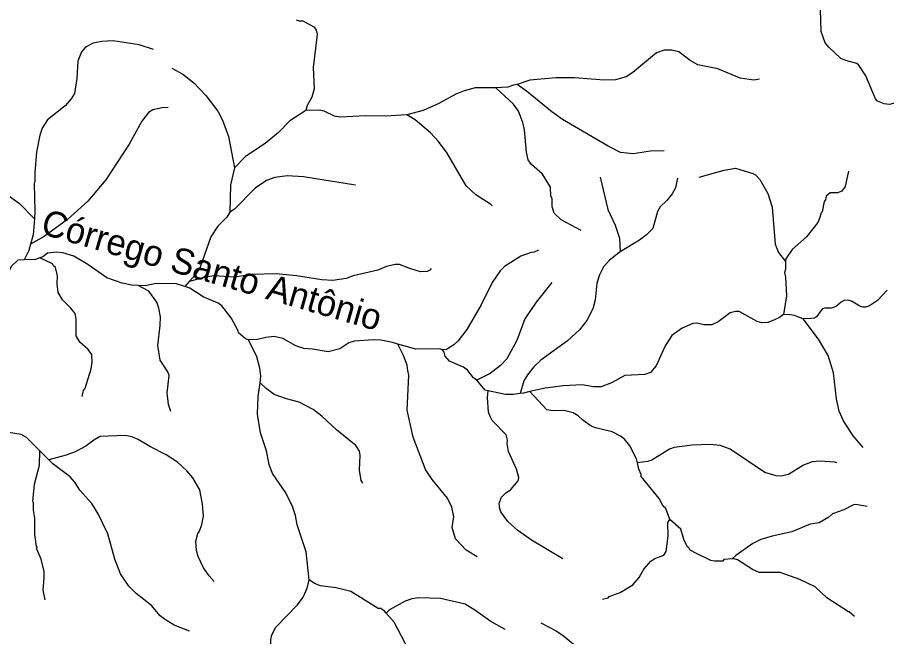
# Model space of a CAD drawing. Extents: x 280.4 to 335.6, y 8893.9 to 8949.5.
# Drawn here: x 307.39 to 314.12, y 8941.25 to 8946.04 of the extents above; entities that cross this region are included whole.
import ezdxf
from ezdxf.enums import TextEntityAlignment as Align

# ---------------------------------------------------------------- set-up
doc = ezdxf.new("R2010")
doc.units = 0
doc.header["$LTSCALE"] = 0.064
doc.layers.add('61', color=7, linetype='Continuous')
doc.layers.add('7', color=7, linetype='Continuous', lineweight=25)

msp = doc.modelspace()

# ---------------------------------------------------------------- linework, layer by layer
at = {"layer": '7'}
for p, q in [((308.7204, 8943.9928), (308.687, 8943.9546)), ((307.6334, 8942.6142), (307.5641, 8942.683))]:
    msp.add_line(p, q, dxfattribs=at)
for points in [[(314.448, 8945.3983), (314.3467, 8945.4085), (314.2833, 8945.4022), (314.1401, 8945.364), (314.0998, 8945.3684), (314.0476, 8945.3888), (314.0315, 8945.4072), (313.958, 8945.5861), (313.903, 8945.6679), (313.8884, 8945.6805), (313.803, 8945.7029), (313.7647, 8945.7193), (313.6718, 8945.8069), (313.6441, 8945.8408), (313.6111, 8945.9293), (313.6077, 8946.0979), (313.6025, 8946.141)], [(309.548, 8946.0198), (309.571, 8946.0106), (309.6004, 8946.0101), (309.6858, 8945.9654), (309.7023, 8945.938), (309.7103, 8945.9059), (309.6803, 8945.6503), (309.6861, 8945.4853), (309.6704, 8945.419), (309.6341, 8945.3565), (309.6217, 8945.3181)], [(308.4439, 8945.7878), (308.3334, 8945.826), (308.1312, 8945.8548), (308.0423, 8945.85), (307.9774, 8945.8374), (307.9177, 8945.8068), (307.8853, 8945.7716), (307.8572, 8945.6994), (307.8504, 8945.5644), (307.8314, 8945.4491), (307.8063, 8945.4074), (307.7587, 8945.3521), (307.6228, 8945.246), (307.5824, 8945.1796), (307.5635, 8945.1264), (307.537, 8944.9937), (307.5243, 8944.8344), (307.5258, 8944.773), (307.5198, 8944.7505), (307.5258, 8944.537), (307.5217, 8944.4792)], [(313.1337, 8945.5583), (313.0897, 8945.5528), (312.985, 8945.5672), (312.8111, 8945.6395), (312.6579, 8945.6709), (312.5981, 8945.7033), (312.5107, 8945.7699), (312.4524, 8945.7844), (312.3971, 8945.7845), (312.3366, 8945.7643), (312.1549, 8945.6103), (312.1018, 8945.5787), (312.0188, 8945.5543), (311.931, 8945.551), (311.7014, 8945.5701), (311.5576, 8945.5701), (311.3568, 8945.5526), (311.2599, 8945.5173), (311.2588, 8945.5172)], [(308.5856, 8945.6448), (308.6701, 8945.5975), (308.7545, 8945.5312), (308.8493, 8945.4333), (308.9427, 8945.3126), (308.9782, 8945.2431), (309.024, 8945.1166), (309.0714, 8944.8728)], [(311.0925, 8945.4921), (311.0767, 8945.4911), (310.9347, 8945.4932), (310.8474, 8945.4693), (310.7841, 8945.444), (310.6528, 8945.372), (310.5322, 8945.3176), (310.4034, 8945.2835)], [(311.2588, 8945.5172), (311.2291, 8945.5137), (311.1865, 8945.4983), (311.0925, 8945.4921)], [(311.7552, 8944.3894), (311.5992, 8944.4715), (311.5455, 8944.5233), (311.529, 8944.5723), (311.5286, 8944.6353), (311.5194, 8944.6554), (311.5157, 8944.7239), (311.4551, 8944.8248), (311.3694, 8944.9002), (311.345, 8944.9361), (311.3321, 8944.9945), (311.3143, 8945.1678), (311.3013, 8945.2254), (311.268, 8945.311), (311.2295, 8945.367), (311.0925, 8945.4921)], [(312.3964, 8945.0052), (312.2901, 8945.0024), (312.1563, 8944.9818), (312.059, 8944.9918), (311.9638, 8945.0408), (311.61, 8945.2484), (311.5265, 8945.3073), (311.3321, 8945.4676), (311.2588, 8945.5172)], [(306.9119, 8945.3451), (306.985, 8945.155), (307.0241, 8945.013), (307.0618, 8944.9184), (307.102, 8944.8473), (307.2001, 8944.7447), (307.4053, 8944.5982), (307.5217, 8944.4792)], [(308.5582, 8945.3406), (308.5111, 8945.338), (308.4371, 8945.3226), (308.4048, 8945.3022), (308.3525, 8945.2336), (308.2541, 8945.0562), (308.0743, 8944.7802), (307.9339, 8944.6157), (307.7776, 8944.4732), (307.597, 8944.342), (307.4925, 8944.2825)], [(309.6217, 8945.3181), (309.4999, 8945.2379), (309.4115, 8945.1466), (309.3088, 8945.0611), (309.1569, 8944.962), (309.0714, 8944.8728)], [(310.4034, 8945.2835), (310.4029, 8945.2834), (310.2437, 8945.2727), (310.0814, 8945.2758), (309.8911, 8945.2663), (309.8438, 8945.2742), (309.7638, 8945.3107), (309.7272, 8945.3207), (309.6217, 8945.3181)], [(311.0653, 8944.5792), (311.0534, 8944.592), (310.9382, 8944.6641), (310.8634, 8944.7337), (310.7166, 8944.9873), (310.6489, 8945.0772), (310.5868, 8945.143), (310.47, 8945.2457), (310.4034, 8945.2835)], [(309.0714, 8944.8728), (309.0387, 8944.741), (309.0334, 8944.5305)], [(312.6678, 8944.8006), (312.8619, 8944.855), (312.9488, 8944.8696), (313.0826, 8944.8298), (313.1023, 8944.8188), (313.1381, 8944.784), (313.198, 8944.6752), (313.2319, 8944.569), (313.2558, 8944.2826), (313.2828, 8944.2178), (313.3355, 8944.1488)], [(310.0082, 8944.7405), (309.6057, 8944.804), (309.4785, 8944.812), (309.3833, 8944.7994), (309.3192, 8944.7757), (309.2304, 8944.7171), (309.0695, 8944.5536), (309.0334, 8944.5305)], [(311.9014, 8944.8023), (311.9605, 8944.5522), (312.0167, 8944.4291), (312.05, 8944.3291), (312.0566, 8944.2245)], [(313.824, 8944.8469), (313.7967, 8944.7285), (313.7716, 8944.6919), (313.738, 8944.6797), (313.6803, 8944.6789), (313.6503, 8944.6529), (313.6459, 8944.6267), (313.6353, 8944.6122), (313.6205, 8944.532), (313.6116, 8944.5255), (313.6027, 8944.4884), (313.5849, 8944.4516), (313.4992, 8944.339), (313.3882, 8944.2422), (313.3396, 8944.1696), (313.3355, 8944.1488)], [(312.4997, 8944.7943), (312.4832, 8944.7187), (312.4582, 8944.6719), (312.4205, 8944.6244), (312.3661, 8944.5716), (312.3441, 8944.5364), (312.3091, 8944.4049), (312.261, 8944.3546), (312.2054, 8944.3128), (312.0566, 8944.2245)], [(309.0334, 8944.5305), (309.0113, 8944.4907), (308.9423, 8944.4212), (308.8876, 8944.3396), (308.8048, 8944.1046), (308.7678, 8944.047), (308.7204, 8943.9928)], [(307.5217, 8944.4792), (307.513, 8944.3552), (307.4925, 8944.2825)], [(307.4925, 8944.2825), (307.4785, 8944.233), (307.4435, 8944.1612)], [(307.6919, 8944.2204), (307.6228, 8944.2136), (307.5861, 8944.1858), (307.5639, 8944.1774)], [(308.3245, 8943.9627), (308.2766, 8943.9644), (308.2007, 8943.98), (308.0825, 8944.023), (307.9362, 8944.1248), (307.828, 8944.1892), (307.7416, 8944.2164), (307.6919, 8944.2204)], [(311.4248, 8944.2364), (311.39, 8944.2199), (311.3663, 8944.2188), (311.2882, 8944.1912), (311.1616, 8944.1103), (311.1282, 8944.0773), (311.0649, 8943.9868), (310.9805, 8943.8143), (310.8678, 8943.6217), (310.8021, 8943.5354), (310.7692, 8943.5045), (310.7106, 8943.4685), (310.6806, 8943.4658)], [(312.0566, 8944.2245), (312.0341, 8944.2074), (312.0075, 8944.1857), (311.9739, 8944.1584), (311.927, 8944.1084), (311.8956, 8944.046), (311.8762, 8943.982), (311.8628, 8943.8518), (311.8453, 8943.7827), (311.7974, 8943.6927), (311.7417, 8943.6209), (311.6484, 8943.5353), (311.443, 8943.386), (311.3869, 8943.3347), (311.3379, 8943.2719), (311.3113, 8943.2256), (311.2827, 8943.1279)], [(307.4435, 8944.1612), (307.3933, 8944.1594), (307.3438, 8944.1134), (307.283, 8943.9907), (307.2366, 8943.9328), (307.1765, 8943.8841), (307.0509, 8943.8141), (307.0063, 8943.7806)], [(307.5639, 8944.1774), (307.5297, 8944.1644), (307.4435, 8944.1612)], [(307.8915, 8943.1039), (307.9011, 8943.1502), (307.9142, 8943.1689), (307.9608, 8943.3191), (307.9687, 8943.367), (307.9654, 8943.4303), (307.9388, 8943.4666), (307.8721, 8943.5239), (307.8444, 8943.573), (307.844, 8943.7054), (307.8377, 8943.7456), (307.804, 8943.7885), (307.7397, 8943.8516), (307.7065, 8943.9077), (307.6971, 8943.976), (307.7015, 8944.0387), (307.6855, 8944.102), (307.6696, 8944.114), (307.6619, 8944.1302), (307.5639, 8944.1774)], [(310.5924, 8944.0957), (310.5835, 8944.0827), (310.5619, 8944.0713), (310.5108, 8944.0694), (310.4265, 8944.0936), (310.3474, 8944.1254), (310.314, 8944.126), (310.248, 8944.1111), (310.1793, 8944.0813), (309.9904, 8944.0379), (309.9337, 8944.0184), (309.831, 8944.0029), (309.7467, 8944.0057), (309.5513, 8944.0381), (309.3914, 8944.054), (309.2019, 8944.0477), (309.073, 8944.0285), (308.9094, 8944.0377), (308.8483, 8944.0284), (308.7204, 8943.9928)], [(313.3355, 8944.1488), (313.3354, 8944.0904), (313.3283, 8944.0637), (313.3359, 8944.0284), (313.3439, 8943.8838), (313.3215, 8943.7398)], [(308.687, 8943.9546), (308.6228, 8943.9757), (308.4645, 8943.9772), (308.3781, 8943.9608), (308.3245, 8943.9627)], [(308.5779, 8942.9872), (308.5591, 8943.0427), (308.5495, 8943.1321), (308.5635, 8943.2669), (308.5546, 8943.2942), (308.4951, 8943.3856), (308.476, 8943.4981), (308.4964, 8943.6535), (308.4965, 8943.7213), (308.4855, 8943.7878), (308.4705, 8943.8339), (308.4069, 8943.9179), (308.3245, 8943.9627)], [(309.1795, 8943.5417), (309.1565, 8943.5496), (309.1024, 8943.5963), (309.0992, 8943.6123), (309.0435, 8943.7124), (308.9715, 8943.806), (308.9453, 8943.8255), (308.8277, 8943.8758), (308.724, 8943.9424), (308.687, 8943.9546)], [(311.5257, 8943.9866), (311.4049, 8943.8345), (311.3179, 8943.7047), (311.2565, 8943.5384), (311.1796, 8943.3946), (311.1302, 8943.3435), (311.0492, 8943.2822), (310.9452, 8943.2304)], [(314.1228, 8943.9261), (314.047, 8943.8457), (313.9858, 8943.805), (313.9563, 8943.7951), (313.9336, 8943.7947), (313.9103, 8943.8021), (313.8454, 8943.8411), (313.8181, 8943.8491), (313.7896, 8943.8461), (313.7671, 8943.8347), (313.7304, 8943.8036), (313.7082, 8943.7924), (313.6882, 8943.7869), (313.6405, 8943.7869), (313.6222, 8943.7819), (313.6105, 8943.768), (313.5754, 8943.7214), (313.5605, 8943.7114), (313.5324, 8943.7069), (313.4738, 8943.7063)], [(313.3215, 8943.7398), (313.2884, 8943.7147), (313.2462, 8943.6936), (313.1985, 8943.677), (313.153, 8943.6748), (313.1163, 8943.6834), (312.9762, 8943.7625), (312.9488, 8943.7629), (312.9064, 8943.7519), (312.8155, 8943.6827), (312.7649, 8943.6596), (312.7058, 8943.6591), (312.6482, 8943.6717), (312.6195, 8943.6684), (312.5356, 8943.6317), (312.4549, 8943.5758), (312.4036, 8943.4974), (312.3335, 8943.3414), (312.2916, 8943.2891), (312.2457, 8943.2732), (312.0916, 8943.267), (311.9895, 8943.2089), (311.9077, 8943.178), (311.8494, 8943.1777), (311.7615, 8943.1936), (311.6168, 8943.1871), (311.4743, 8943.168), (311.3568, 8943.1421)], [(313.4738, 8943.7063), (313.4306, 8943.7214), (313.4047, 8943.7312), (313.3751, 8943.7369), (313.3215, 8943.7398)], [(313.9366, 8942.7093), (313.8589, 8942.8003), (313.7835, 8942.9156), (313.751, 8942.9899), (313.7293, 8943.0855), (313.7083, 8943.287), (313.6669, 8943.4207), (313.5913, 8943.5476), (313.4738, 8943.7063)], [(310.3346, 8943.5094), (310.2927, 8943.5215), (310.2029, 8943.5403), (310.143, 8943.5438), (309.9971, 8943.5319), (309.9551, 8943.5196), (309.8847, 8943.4736), (309.7968, 8943.4497), (309.6752, 8943.4716), (309.608, 8943.4756), (309.545, 8943.4962), (309.4442, 8943.552), (309.3777, 8943.5675), (309.3121, 8943.5614), (309.2482, 8943.544), (309.1795, 8943.5417)], [(309.2683, 8943.2096), (309.2751, 8943.2605), (309.2674, 8943.324), (309.2437, 8943.4104), (309.1795, 8943.5417)], [(310.6806, 8943.4658), (310.6583, 8943.4732), (310.4749, 8943.4691), (310.3346, 8943.5094)], [(310.9498, 8941.8639), (310.863, 8941.9163), (310.7819, 8942.0029), (310.7565, 8942.0908), (310.7673, 8942.1719), (310.7528, 8942.2475), (310.7195, 8942.3172), (310.6007, 8942.4618), (310.5489, 8942.5405), (310.4532, 8942.7904), (310.4078, 8942.9978), (310.4189, 8943.2688), (310.413, 8943.3062), (310.4066, 8943.3473), (310.3785, 8943.4214), (310.3346, 8943.5094)], [(310.9452, 8943.2304), (310.9206, 8943.2475), (310.8741, 8943.3075), (310.8442, 8943.331), (310.7347, 8943.3774), (310.7008, 8943.4157), (310.6923, 8943.4481), (310.6806, 8943.4658)], [(309.6473, 8941.6848), (309.6256, 8941.9014), (309.5555, 8942.1118), (309.5424, 8942.1829), (309.52, 8942.2532), (309.4677, 8942.3582), (309.3634, 8942.5092), (309.338, 8942.5788), (309.3173, 8942.6833), (309.2726, 8942.8242), (309.2484, 8942.9665), (309.2543, 8943.1042), (309.2683, 8943.2096)], [(310.0635, 8942.4347), (310.052, 8942.4552), (310.0385, 8942.5348), (310.0445, 8942.6505), (310.0381, 8942.6818), (310.0104, 8942.7253), (309.8603, 8942.8454), (309.747, 8942.9519), (309.68, 8943.0033), (309.5706, 8943.061), (309.472, 8943.0859), (309.3782, 8943.1207), (309.3147, 8943.1667), (309.2683, 8943.2096)], [(311.0354, 8943.148), (311.011, 8943.1532), (310.9452, 8943.2304)], [(311.613, 8941.8478), (311.3695, 8941.9938), (311.2644, 8942.0668), (311.187, 8942.1378), (311.1331, 8942.213), (311.1241, 8942.2347), (311.1195, 8942.2788), (311.1362, 8942.3258), (311.1674, 8942.3556), (311.2099, 8942.3838), (311.2674, 8942.4509), (311.2709, 8942.4764), (311.2536, 8942.5411), (311.1906, 8942.6778), (311.1807, 8942.7401), (311.183, 8942.7675), (311.1734, 8942.8064), (311.0644, 8942.9174), (311.0527, 8942.9454), (311.0374, 8942.982), (311.0282, 8943.0969), (311.0354, 8943.148)], [(311.2827, 8943.1279), (311.2269, 8943.1205), (311.1673, 8943.1201), (311.0354, 8943.148)], [(311.3568, 8943.1421), (311.3068, 8943.1311), (311.2827, 8943.1279)], [(312.1896, 8942.5914), (312.1826, 8942.6214), (312.1316, 8942.7234), (312.0899, 8942.7732), (312.0598, 8942.798), (311.9941, 8942.8316), (311.8661, 8942.8621), (311.8327, 8942.8754), (311.7669, 8942.9206), (311.7303, 8942.9547), (311.6922, 8942.9771), (311.6205, 8942.9952), (311.5359, 8942.9922), (311.4888, 8943.002), (311.3568, 8943.1421)], [(307.5641, 8942.683), (307.4594, 8942.7869), (307.4187, 8942.8101), (307.1068, 8942.8597), (306.9045, 8942.9112)], [(308.914, 8941.674), (308.8744, 8941.717), (308.831, 8941.7789), (308.788, 8941.8656), (308.7762, 8941.9125), (308.7721, 8941.984), (308.7879, 8942.0452), (308.8003, 8942.063), (308.8182, 8942.1132), (308.8306, 8942.179), (308.8225, 8942.2717), (308.8019, 8942.3812), (308.7476, 8942.4739), (308.7012, 8942.5299), (308.6282, 8942.5951), (308.5423, 8942.6518), (308.4197, 8942.7138), (308.3236, 8942.7722), (308.2765, 8942.7919), (308.2253, 8942.8032), (308.0313, 8942.7937), (307.9809, 8942.7673), (307.9192, 8942.7203), (307.837, 8942.6769), (307.7666, 8942.6492), (307.6334, 8942.6142)], [(313.7343, 8942.5901), (313.7167, 8942.5964), (313.6045, 8942.6035), (313.5427, 8942.5976), (313.4761, 8942.5728), (313.3599, 8942.5012), (313.3034, 8942.4868), (313.2623, 8942.49), (313.1759, 8942.516), (312.9073, 8942.6962), (312.829, 8942.7262), (312.7493, 8942.7331), (312.6145, 8942.7281), (312.4748, 8942.7104), (312.4375, 8942.6978), (312.3011, 8942.6126), (312.2676, 8942.602), (312.1896, 8942.5914)], [(307.6042, 8941.5312), (307.5882, 8941.6065), (307.5977, 8941.7031), (307.5963, 8941.7498), (307.5744, 8941.8449), (307.5405, 8941.9223), (307.5431, 8941.936), (307.537, 8941.9435), (307.5259, 8942.0351), (307.5242, 8942.1631), (307.5149, 8942.2245), (307.5146, 8942.2825), (307.5085, 8942.2909), (307.5211, 8942.4259), (307.56, 8942.5716), (307.5641, 8942.683)], [(308.7217, 8941.2883), (308.6032, 8941.3347), (308.5286, 8941.3801), (308.4946, 8941.4079), (308.4282, 8941.4881), (308.3089, 8941.5807), (308.2526, 8941.6354), (308.1889, 8941.7332), (308.145, 8941.8464), (308.0908, 8942.0408), (308.0164, 8942.1963), (307.9674, 8942.2751), (307.8729, 8942.3787), (307.8356, 8942.4422), (307.7996, 8942.483), (307.665, 8942.5829), (307.6334, 8942.6142)], [(312.4411, 8942.1528), (312.4091, 8942.2375), (312.3898, 8942.2544), (312.3582, 8942.3141), (312.2187, 8942.4847), (312.2193, 8942.4994), (312.201, 8942.5427), (312.1896, 8942.5914)], [(313.9668, 8942.2526), (313.8803, 8942.2674), (313.8623, 8942.2655), (313.7875, 8942.228), (313.7007, 8942.1953), (313.6722, 8942.17), (313.5965, 8942.127), (313.5274, 8942.1171), (313.3854, 8942.0566), (313.2331, 8942.0243), (313.1451, 8941.9965), (313.0838, 8941.9673), (312.9525, 8941.8743), (312.9234, 8941.847)], [(311.9181, 8941.5352), (311.9631, 8941.5461), (311.9709, 8941.5559), (312.0551, 8941.5873), (312.1545, 8941.6476), (312.2042, 8941.7036), (312.2389, 8941.767), (312.2938, 8941.83), (312.3236, 8941.85), (312.3928, 8941.8771), (312.411, 8941.9055), (312.4275, 8942.0269), (312.4261, 8942.1287), (312.4411, 8942.1528)], [(312.9234, 8941.847), (312.8591, 8941.8432), (312.8499, 8941.8293), (312.7855, 8941.8293), (312.7585, 8941.8359), (312.6355, 8941.8935), (312.5963, 8941.919), (312.5876, 8941.9343), (312.5759, 8941.9409), (312.5511, 8941.9902), (312.5244, 8942.0777), (312.4411, 8942.1528)], [(313.8706, 8941.4011), (313.8285, 8941.438), (313.8223, 8941.4368), (313.6554, 8941.5455), (313.5662, 8941.6311), (313.4478, 8941.6887), (313.295, 8941.7413), (313.1318, 8941.7415), (313.0791, 8941.7662), (312.9643, 8941.8416), (312.9372, 8941.8478), (312.9234, 8941.847)], [(309.7774, 8940.5149), (309.599, 8940.6041), (309.4311, 8940.7223), (309.3664, 8940.7812), (309.3459, 8940.8715), (309.3537, 8940.9978), (309.3506, 8941.2233), (309.3587, 8941.2599), (309.3895, 8941.3199), (309.5582, 8941.4916), (309.6012, 8941.5505), (309.6333, 8941.6224), (309.6473, 8941.6848)], [(310.2458, 8941.4287), (310.2346, 8941.4417), (310.2029, 8941.4638), (310.1825, 8941.4639), (309.971, 8941.5942), (309.8575, 8941.6228), (309.7368, 8941.6394), (309.69, 8941.6571), (309.6473, 8941.6848)], [(311.1657, 8941.3024), (311.056, 8941.3621), (310.9322, 8941.452), (310.8561, 8941.4979), (310.6659, 8941.5404), (310.4967, 8941.5464), (310.4445, 8941.5384), (310.3923, 8941.5195), (310.2699, 8941.4526), (310.2458, 8941.4287)], [(310.9949, 8940.3334), (310.8398, 8940.4116), (310.7843, 8940.4459), (310.783, 8940.4553), (310.7752, 8940.4582), (310.7442, 8940.5003), (310.711, 8940.5622), (310.6859, 8940.6268), (310.656, 8940.7578), (310.6307, 8940.828), (310.4189, 8941.1418), (310.3073, 8941.357), (310.2458, 8941.4287)], [(311.441, 8941.354), (311.5607, 8941.2905), (311.6173, 8941.2517), (311.704, 8941.179), (311.7505, 8941.1674), (311.8277, 8941.1272), (311.9302, 8941.0504), (311.9998, 8940.9717), (312.0397, 8940.8712), (312.0926, 8940.6588), (312.146, 8940.5612), (312.2164, 8940.4621), (312.2325, 8940.4291), (312.2369, 8940.3343), (312.1766, 8940.2668), (312.1577, 8940.2265), (312.1689, 8940.1375)]]:
    msp.add_lwpolyline(points, dxfattribs=at)

# ---------------------------------------------------------------- texts
at = {"layer": '61'}
msp.add_text('Córrego Santo Antônio', height=0.2, rotation=343.876, dxfattribs=at).set_placement((308.868, 8943.9881), align=Align.CENTER)

doc.saveas('drawing.dxf')
